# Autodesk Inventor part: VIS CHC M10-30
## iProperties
Created: 2004-11
Part Number: VIS CHC M10-30
Document SubType Name: Modeling
Designer: Bruno
Manufacturer: Standard
Standards Organization: Custom
Author: Bruno
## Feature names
1. Base1
